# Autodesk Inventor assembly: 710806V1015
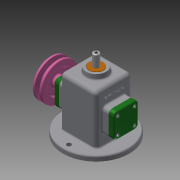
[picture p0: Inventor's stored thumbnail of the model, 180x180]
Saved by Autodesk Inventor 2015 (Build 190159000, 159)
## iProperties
Created: 2021-08
Part Number: 710806V1015
Document SubType Name: Assembly
Designer: 1054878
Author: 1054878
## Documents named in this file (16)
- C:\Users\1054878\Desktop\710806V1015 (1)\710806V1015.iam
- C:\Users\1054878\Desktop\710806V1015 (1)\V벨트풀리.ipt
- C:\Users\1054878\Desktop\710806V1015 (1)\고정핀 1.2x8.ipt
- C:\Users\1054878\Desktop\710806V1015 (1)\뒤커버.ipt
- C:\Users\1054878\Desktop\710806V1015 (1)\링크.ipt
- C:\Users\1054878\Desktop\710806V1015 (1)\멈춤나사 M3x8.ipt
- C:\Users\1054878\Desktop\710806V1015 (1)\베어링 12x32x10.ipt
- C:\Users\1054878\Desktop\710806V1015 (1)\본체.ipt
- C:\Users\1054878\Desktop\710806V1015 (1)\볼트 M4.ipt
- C:\Users\1054878\Desktop\710806V1015 (1)\부시.ipt
- C:\Users\1054878\Desktop\710806V1015 (1)\슬라이드.ipt
- C:\Users\1054878\Desktop\710806V1015 (1)\앞커버.ipt
- C:\Users\1054878\Desktop\710806V1015 (1)\오일 실 12 25 7.ipt
- C:\Users\1054878\Desktop\710806V1015 (1)\키 4x4x10.ipt
- C:\Users\1054878\Desktop\710806V1015 (1)\편심축.ipt
- C:\Users\1054878\Desktop\710806V1015 (1)\핀 5x18.ipt
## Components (3 placed, 3 different names)
1. V벨트풀리:1 — 각도:2
2. 고정핀 1.2x8:1
3. 핀 5x18:1
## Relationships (1: Angle 1)
- 각도:2 [Angle]: V벨트풀리:1
